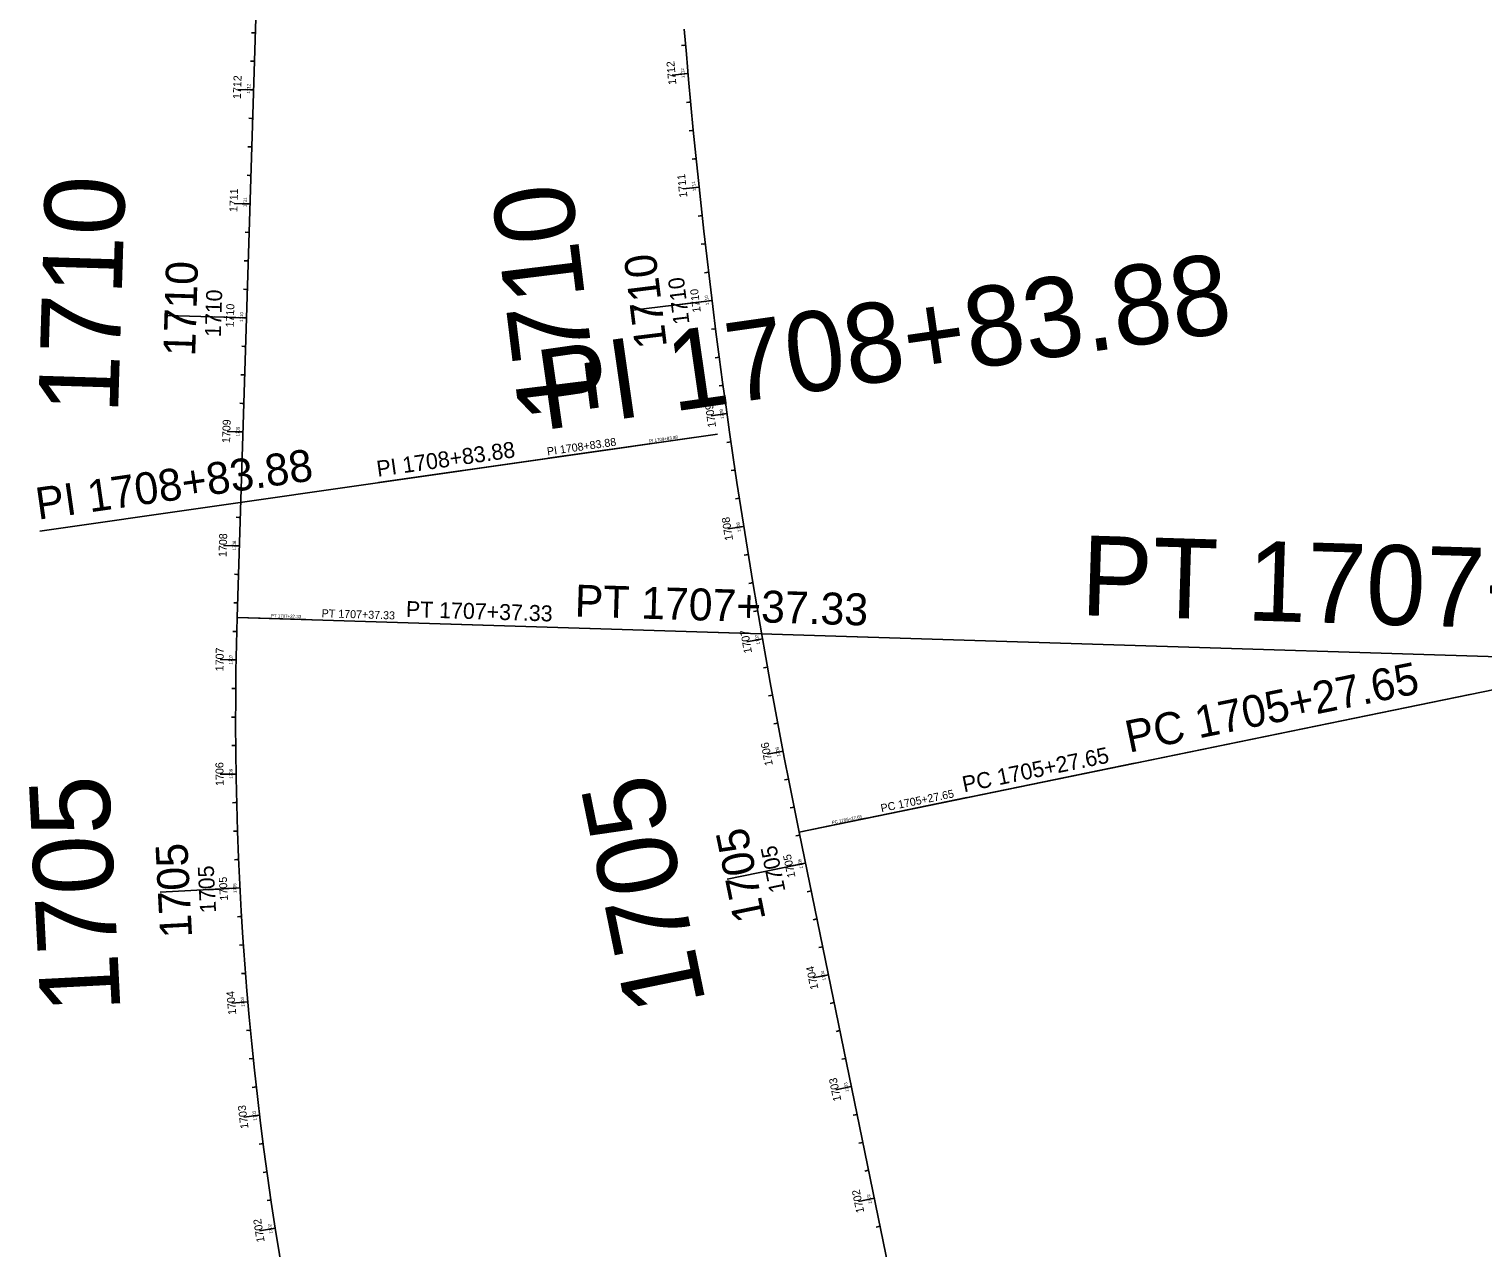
# Model space of a CAD drawing. Extents: x 353835 to 363333, y 126218 to 205387.
# Drawn here: x 361189 to 362463, y 129386 to 130454 of the extents above; entities that cross this region are included whole.
import ezdxf

# ---------------------------------------------------------------- set-up
doc = ezdxf.new("R2010")
doc.units = 0
for name, color, linetype in [('P_ALI_100_PIData', 7, 'Continuous'), ('P_ALI_100_Sta', 7, 'Continuous'), ('P_ALI_100_Tic', 7, 'Continuous'), ('P_ALI_20', 7, 'Continuous'), ('P_ALI_200_PIData', 7, 'Continuous'), ('P_ALI_200_Sta', 7, 'Continuous'), ('P_ALI_200_Tic', 7, 'Continuous'), ('P_ALI_20_PIData', 7, 'Continuous'), ('P_ALI_20_Sta', 7, 'Continuous'), ('P_ALI_20_Tic', 7, 'Continuous'), ('P_ALI_500_PIData', 7, 'Continuous'), ('P_ALI_500_Sta', 7, 'Continuous'), ('P_ALI_50_PIData', 7, 'Continuous'), ('P_ALI_50_Sta', 7, 'Continuous'), ('P_ALI_50_Tic', 7, 'Continuous')]:
    doc.layers.add(name, color=color, linetype=linetype)

msp = doc.modelspace()

# ---------------------------------------------------------------- linework, layer by layer
for points in [[(361766.2, 130415), (361766.3, 130415)], [(361775.9, 130315.4), (361775.9, 130315.5)], [(361800.3, 130117), (361800.4, 130117)], [(361815.1, 130018), (361815.1, 130018)], [(361831.5, 129919.4), (361831.5, 129919.4)], [(361849.5, 129821), (361849.6, 129821.1)], [(361889.3, 129625), (361889.3, 129625.1)], [(361909.4, 129527.1), (361909.5, 129527.1)], [(361929.5, 129429.1), (361929.6, 129429.1)]]:
    msp.add_lwpolyline(points)
at = {"layer": 'P_ALI_100_PIData'}
for points in [[(361792, 130099), (361495.1, 130056.5)], [(361792, 130099), (361732.6, 130090.5)], [(361371.2, 129938.3), (361671, 129929)], [(361371.2, 129938.3), (361431.2, 129936.4)], [(361863.7, 129750.1), (362157.5, 129810.4)], [(361863.7, 129750.1), (361922.4, 129762.2)]]:
    msp.add_lwpolyline(points, dxfattribs=at)
at = {"layer": 'P_ALI_100_Tic'}
for points in [[(361759.3, 130414.4), (361766.3, 130415)], [(361378.6, 130401), (361385.6, 130400.8)], [(361769, 130314.7), (361775.9, 130315.4)], [(361375.5, 130301), (361382.5, 130300.8)], [(361717.8, 130207.6), (361787.3, 130216.1)], [(361773.4, 130214.4), (361787.3, 130216.1)], [(361309.4, 130203.1), (361379.4, 130200.9)], [(361365.4, 130201.3), (361379.4, 130200.9)], [(361793.4, 130116), (361800.4, 130117)], [(361369.3, 130101.1), (361376.3, 130100.9)], [(361808.2, 130017), (361815.1, 130018)], [(361366.1, 130001.2), (361373.1, 130001)], [(361824.6, 129918.2), (361831.5, 129919.4)], [(361363.3, 129901.1), (361370.3, 129901)], [(361842.7, 129819.7), (361849.6, 129821.1)], [(361363.2, 129800.9), (361370.2, 129801)], [(361800.7, 129708.9), (361869.2, 129723)], [(361855.5, 129720.2), (361869.2, 129723)], [(361303.7, 129697.5), (361373.6, 129701.1)], [(361359.6, 129700.4), (361373.6, 129701.1)], [(361882.5, 129623.6), (361889.3, 129625)], [(361373.5, 129600.7), (361380.4, 129601.3)], [(361902.6, 129525.7), (361909.4, 129527.1)], [(361383.8, 129501), (361390.8, 129501.9)], [(361922.7, 129427.7), (361929.6, 129429.1)], [(361397.6, 129401.7), (361404.6, 129402.8)]]:
    msp.add_lwpolyline(points, dxfattribs=at)
at = {"layer": 'P_ALI_20'}
for p, q in [((361371.2, 129938.3), (361462, 132847.8)), ((362324.5, 127505.2), (361863.7, 129750.1))]:
    msp.add_line(p, q, dxfattribs=at)
for centre, radius, start, end in [((367643.2, 130936.5), 5900, 184.68978, 191.60009), ((364244.8, 129848.6), 2875, 178.2122, 207.9813)]:
    msp.add_arc(centre, radius, start, end, dxfattribs=at)
at = {"layer": 'P_ALI_200_PIData'}
for points in [[(361792, 130099), (361198.1, 130014)], [(361371.2, 129938.3), (361970.9, 129919.6)], [(361863.7, 129750.1), (362451.4, 129870.7)]]:
    msp.add_lwpolyline(points, dxfattribs=at)
at = {"layer": 'P_ALI_200_Tic'}
for points in [[(361752.3, 130413.7), (361766.3, 130415)], [(361371.6, 130401.2), (361385.6, 130400.8)], [(361762, 130314), (361775.9, 130315.4)], [(361368.5, 130301.3), (361382.5, 130300.8)], [(361759.5, 130212.7), (361787.3, 130216.1)], [(361351.4, 130201.7), (361379.4, 130200.9)], [(361786.5, 130115), (361800.4, 130117)], [(361362.3, 130101.4), (361376.3, 130100.9)], [(361801.3, 130015.9), (361815.1, 130018)], [(361359.1, 130001.4), (361373.1, 130001)], [(361817.7, 129917), (361831.5, 129919.4)], [(361356.3, 129901.3), (361370.3, 129901)], [(361835.8, 129818.4), (361849.6, 129821.1)], [(361356.2, 129800.8), (361370.2, 129801)], [(361841.8, 129717.4), (361869.2, 129723)], [(361345.6, 129699.6), (361373.6, 129701.1)], [(361875.6, 129622.2), (361889.3, 129625)], [(361366.5, 129600.1), (361380.4, 129601.3)], [(361895.7, 129524.3), (361909.4, 129527.1)], [(361376.9, 129500.2), (361390.8, 129501.9)], [(361915.8, 129426.3), (361929.6, 129429.1)], [(361390.7, 129400.6), (361404.6, 129402.8)]]:
    msp.add_lwpolyline(points, dxfattribs=at)
at = {"layer": 'P_ALI_20_Tic'}
for points in [[(361385.8, 130450.8), (361387.2, 130450.7)], [(361762.7, 130439.8), (361764.1, 130439.9)], [(361385, 130425.8), (361386.4, 130425.8)], [(361763.5, 130414.7), (361766.3, 130415)], [(361382.8, 130400.9), (361385.6, 130400.8)], [(361767.1, 130390), (361768.5, 130390.1)], [(361383.4, 130375.8), (361384.8, 130375.8)], [(361769.5, 130365.1), (361770.9, 130365.2)], [(361382.7, 130350.8), (361384.1, 130350.8)], [(361772, 130340.2), (361773.4, 130340.3)], [(361381.9, 130325.8), (361383.3, 130325.8)], [(361773.2, 130315.2), (361775.9, 130315.4)], [(361379.7, 130300.9), (361382.5, 130300.8)], [(361777.2, 130290.4), (361778.6, 130290.6)], [(361380.3, 130275.9), (361381.7, 130275.8)], [(361780, 130265.6), (361781.4, 130265.8)], [(361379.5, 130250.9), (361380.9, 130250.8)], [(361782.9, 130240.8), (361784.3, 130240.9)], [(361378.8, 130225.9), (361380.2, 130225.9)], [(361784.5, 130215.8), (361787.3, 130216.1)], [(361376.6, 130201), (361379.4, 130200.9)], [(361789, 130191.1), (361790.4, 130191.3)], [(361377.2, 130175.9), (361378.6, 130175.9)], [(361792.2, 130166.3), (361793.6, 130166.5)], [(361376.4, 130150.9), (361377.8, 130150.9)], [(361795.5, 130141.5), (361796.9, 130141.7)], [(361375.6, 130125.9), (361377, 130125.9)], [(361797.6, 130116.6), (361800.4, 130117)], [(361373.5, 130101), (361376.3, 130100.9)], [(361802.5, 130092), (361803.9, 130092.2)], [(361374.1, 130076), (361375.5, 130075.9)], [(361806.1, 130067.3), (361807.5, 130067.5)], [(361373.3, 130051), (361374.7, 130050.9)], [(361809.9, 130042.5), (361811.2, 130042.8)], [(361372.5, 130026), (361373.9, 130026)], [(361812.3, 130017.6), (361815.1, 130018)], [(361370.3, 130001.1), (361373.1, 130001)], [(361817.6, 129993.1), (361819, 129993.4)], [(361371, 129976), (361372.4, 129976)], [(361821.7, 129968.5), (361823.1, 129968.7)], [(361370.2, 129951), (361371.6, 129951)], [(361825.8, 129943.8), (361827.2, 129944)], [(361369.4, 129926), (361370.8, 129926)], [(361828.7, 129918.9), (361831.5, 129919.4)], [(361367.5, 129901.1), (361370.3, 129901)], [(361834.5, 129894.5), (361835.8, 129894.8)], [(361368.5, 129876), (361369.9, 129876)], [(361838.9, 129869.9), (361840.3, 129870.2)], [(361368.4, 129851), (361369.8, 129851)], [(361843.5, 129845.4), (361844.9, 129845.6)], [(361368.5, 129826), (361369.9, 129826)], [(361846.8, 129820.5), (361849.6, 129821.1)], [(361367.4, 129801), (361370.2, 129801)], [(361853, 129796.2), (361854.3, 129796.5)], [(361369.3, 129776), (361370.7, 129776)], [(361857.8, 129771.7), (361859.2, 129772)], [(361370, 129751), (361371.4, 129751)], [(361862.8, 129747.2), (361864.2, 129747.5)], [(361371, 129726), (361372.4, 129726)], [(361866.5, 129722.4), (361869.2, 129723)], [(361370.8, 129700.9), (361373.6, 129701.1)], [(361872.9, 129698.2), (361874.3, 129698.5)], [(361373.6, 129676), (361375, 129676.1)], [(361877.9, 129673.7), (361879.3, 129674)], [(361375.2, 129651.1), (361376.6, 129651.2)], [(361882.9, 129649.3), (361884.3, 129649.5)], [(361377, 129626.1), (361378.4, 129626.2)], [(361886.6, 129624.5), (361889.3, 129625)], [(361377.7, 129601.1), (361380.4, 129601.3)], [(361893, 129600.3), (361894.4, 129600.6)], [(361381.3, 129576.3), (361382.7, 129576.4)], [(361898, 129575.8), (361899.4, 129576.1)], [(361383.8, 129551.4), (361385.2, 129551.5)], [(361903, 129551.3), (361904.4, 129551.6)], [(361386.5, 129526.5), (361387.9, 129526.7)], [(361906.7, 129526.5), (361909.4, 129527.1)], [(361388, 129501.5), (361390.8, 129501.9)], [(361913.1, 129502.3), (361914.5, 129502.6)], [(361392.5, 129476.9), (361393.9, 129477.1)], [(361918.1, 129477.8), (361919.5, 129478.1)], [(361395.9, 129452.1), (361397.2, 129452.3)], [(361923.2, 129453.3), (361924.5, 129453.6)], [(361926.8, 129428.6), (361929.6, 129429.1)], [(361399.4, 129427.3), (361400.8, 129427.5)], [(361933.2, 129404.4), (361934.6, 129404.6)], [(361401.8, 129402.4), (361404.6, 129402.8)]]:
    msp.add_lwpolyline(points, dxfattribs=at)
at = {"layer": 'P_ALI_500_PIData'}
for points in [[(361792, 130099), (361643.6, 130077.8)], [(361863.7, 129750.1), (363333, 130051.7)], [(361371.2, 129938.3), (362870.5, 129891.5)]]:
    msp.add_lwpolyline(points, dxfattribs=at)
at = {"layer": 'P_ALI_50_PIData'}
for points in [[(361792, 130099), (361643.6, 130077.8)], [(361371.2, 129938.3), (361521.1, 129933.6)], [(361371.2, 129938.3), (361521.1, 129933.6)], [(361863.7, 129750.1), (362010.6, 129780.3)]]:
    msp.add_lwpolyline(points, dxfattribs=at)
at = {"layer": 'P_ALI_50_Tic'}
for points in [[(361383.7, 130450.9), (361387.2, 130450.7)], [(361383.7, 130450.9), (361387.2, 130450.7)], [(361760.6, 130439.6), (361764.1, 130439.9)], [(361382.9, 130425.9), (361386.4, 130425.8)], [(361382.9, 130425.9), (361386.4, 130425.8)], [(361759.3, 130414.4), (361766.3, 130415)], [(361378.6, 130401), (361385.6, 130400.8)], [(361378.6, 130401), (361385.6, 130400.8)], [(361765, 130389.8), (361768.5, 130390.1)], [(361381.3, 130375.9), (361384.8, 130375.8)], [(361381.3, 130375.9), (361384.8, 130375.8)], [(361767.4, 130364.9), (361770.9, 130365.2)], [(361380.6, 130350.9), (361384.1, 130350.8)], [(361380.6, 130350.9), (361384.1, 130350.8)], [(361769.9, 130340), (361773.4, 130340.3)], [(361379.8, 130325.9), (361383.3, 130325.8)], [(361379.8, 130325.9), (361383.3, 130325.8)], [(361769, 130314.7), (361775.9, 130315.4)], [(361375.5, 130301), (361382.5, 130300.8)], [(361375.5, 130301), (361382.5, 130300.8)], [(361775.1, 130290.2), (361778.6, 130290.6)], [(361378.2, 130275.9), (361381.7, 130275.8)], [(361378.2, 130275.9), (361381.7, 130275.8)], [(361777.9, 130265.4), (361781.4, 130265.8)], [(361377.4, 130251), (361380.9, 130250.8)], [(361377.4, 130251), (361380.9, 130250.8)], [(361780.8, 130240.5), (361784.3, 130240.9)], [(361376.7, 130226), (361380.2, 130225.9)], [(361376.7, 130226), (361380.2, 130225.9)], [(361780.4, 130215.2), (361787.3, 130216.1)], [(361372.4, 130201.1), (361379.4, 130200.9)], [(361372.4, 130201.1), (361379.4, 130200.9)], [(361786.9, 130190.9), (361790.4, 130191.3)], [(361375.1, 130176), (361378.6, 130175.9)], [(361375.1, 130176), (361378.6, 130175.9)], [(361790.1, 130166), (361793.6, 130166.5)], [(361374.3, 130151), (361377.8, 130150.9)], [(361374.3, 130151), (361377.8, 130150.9)], [(361793.5, 130141.2), (361796.9, 130141.7)], [(361373.5, 130126), (361377, 130125.9)], [(361373.5, 130126), (361377, 130125.9)], [(361793.4, 130116), (361800.4, 130117)], [(361369.3, 130101.1), (361376.3, 130100.9)], [(361369.3, 130101.1), (361376.3, 130100.9)], [(361800.4, 130091.7), (361803.9, 130092.2)], [(361372, 130076), (361375.5, 130075.9)], [(361372, 130076), (361375.5, 130075.9)], [(361804, 130067), (361807.5, 130067.5)], [(361371.2, 130051), (361374.7, 130050.9)], [(361371.2, 130051), (361374.7, 130050.9)], [(361807.8, 130042.2), (361811.2, 130042.8)], [(361370.4, 130026.1), (361373.9, 130026)], [(361370.4, 130026.1), (361373.9, 130026)], [(361808.2, 130017), (361815.1, 130018)], [(361366.1, 130001.2), (361373.1, 130001)], [(361366.1, 130001.2), (361373.1, 130001)], [(361815.6, 129992.8), (361819, 129993.4)], [(361368.9, 129976.1), (361372.4, 129976)], [(361368.9, 129976.1), (361372.4, 129976)], [(361819.6, 129968.1), (361823.1, 129968.7)], [(361368.1, 129951.1), (361371.6, 129951)], [(361368.1, 129951.1), (361371.6, 129951)], [(361823.8, 129943.4), (361827.2, 129944)], [(361367.3, 129926.1), (361370.8, 129926)], [(361367.3, 129926.1), (361370.8, 129926)], [(361824.6, 129918.2), (361831.5, 129919.4)], [(361363.3, 129901.1), (361370.3, 129901)], [(361363.3, 129901.1), (361370.3, 129901)], [(361832.4, 129894.2), (361835.8, 129894.8)], [(361366.4, 129876), (361369.9, 129876)], [(361366.4, 129876), (361369.9, 129876)], [(361836.9, 129869.6), (361840.3, 129870.2)], [(361366.3, 129851), (361369.8, 129851)], [(361366.3, 129851), (361369.8, 129851)], [(361841.4, 129845), (361844.9, 129845.6)], [(361366.4, 129826), (361369.9, 129826)], [(361366.4, 129826), (361369.9, 129826)], [(361842.7, 129819.7), (361849.6, 129821.1)], [(361363.2, 129800.9), (361370.2, 129801)], [(361363.2, 129800.9), (361370.2, 129801)], [(361850.9, 129795.8), (361854.3, 129796.5)], [(361367.2, 129775.9), (361370.7, 129776)], [(361367.2, 129775.9), (361370.7, 129776)], [(361855.8, 129771.3), (361859.2, 129772)], [(361367.9, 129750.9), (361371.4, 129751)], [(361367.9, 129750.9), (361371.4, 129751)], [(361860.8, 129746.8), (361864.2, 129747.5)], [(361368.9, 129725.9), (361372.4, 129726)], [(361368.9, 129725.9), (361372.4, 129726)], [(361862.4, 129721.6), (361869.2, 129723)], [(361366.6, 129700.7), (361373.6, 129701.1)], [(361366.6, 129700.7), (361373.6, 129701.1)], [(361870.8, 129697.8), (361874.3, 129698.5)], [(361371.5, 129675.9), (361375, 129676.1)], [(361371.5, 129675.9), (361375, 129676.1)], [(361875.9, 129673.3), (361879.3, 129674)], [(361373.1, 129650.9), (361376.6, 129651.2)], [(361373.1, 129650.9), (361376.6, 129651.2)], [(361880.9, 129648.8), (361884.3, 129649.5)], [(361374.9, 129626), (361378.4, 129626.2)], [(361374.9, 129626), (361378.4, 129626.2)], [(361882.5, 129623.6), (361889.3, 129625)], [(361373.5, 129600.7), (361380.4, 129601.3)], [(361373.5, 129600.7), (361380.4, 129601.3)], [(361890.9, 129599.9), (361894.4, 129600.6)], [(361379.2, 129576.1), (361382.7, 129576.4)], [(361379.2, 129576.1), (361382.7, 129576.4)], [(361896, 129575.4), (361899.4, 129576.1)], [(361381.7, 129551.2), (361385.2, 129551.5)], [(361381.7, 129551.2), (361385.2, 129551.5)], [(361901, 129550.9), (361904.4, 129551.6)], [(361384.4, 129526.3), (361387.9, 129526.7)], [(361384.4, 129526.3), (361387.9, 129526.7)], [(361902.6, 129525.7), (361909.4, 129527.1)], [(361383.8, 129501), (361390.8, 129501.9)], [(361383.8, 129501), (361390.8, 129501.9)], [(361911, 129501.9), (361914.5, 129502.6)], [(361390.4, 129476.6), (361393.9, 129477.1)], [(361390.4, 129476.6), (361393.9, 129477.1)], [(361916.1, 129477.4), (361919.5, 129478.1)], [(361393.8, 129451.8), (361397.2, 129452.3)], [(361393.8, 129451.8), (361397.2, 129452.3)], [(361921.1, 129452.9), (361924.5, 129453.6)], [(361922.7, 129427.7), (361929.6, 129429.1)], [(361397.3, 129427), (361400.8, 129427.5)], [(361397.3, 129427), (361400.8, 129427.5)], [(361931.2, 129403.9), (361934.6, 129404.6)], [(361397.6, 129401.7), (361404.6, 129402.8)], [(361397.6, 129401.7), (361404.6, 129402.8)]]:
    msp.add_lwpolyline(points, dxfattribs=at)

# ---------------------------------------------------------------- texts
at = {"layer": 'P_ALI_100_PIData'}
for s, rotation, p in [('PI 1708+83.88', 8.1449, (361494.4, 130061.5)), ('PT 1707+37.33', 358.2122, (361518.9, 129938.7)), ('PC 1705+27.65', 11.6001, (362008.2, 129784.9))]:
    msp.add_text(s, height=14, rotation=rotation, dxfattribs=at).set_placement(p)
at = {"layer": 'P_ALI_100_Sta'}
for s, rotation, p in [('1710', 97.0131, (361767.6, 130195.9)), ('1710', 88.2122, (361356.8, 130183.9)), ('1705', 101.6001, (361851.8, 129698.5)), ('1705', 92.9418, (361352.7, 129679.5))]:
    msp.add_text(s, height=14, rotation=rotation, dxfattribs=at).set_placement(p)
at = {"layer": 'P_ALI_200_PIData'}
for s, rotation, p in [('PI 1708+83.88', 8.1449, (361196.7, 130023.9)), ('PT 1707+37.33', 358.2122, (361666.7, 129939.1)), ('PC 1705+27.65', 11.6001, (362152.7, 129819.6))]:
    msp.add_text(s, height=28, rotation=rotation, dxfattribs=at).set_placement(p)
at = {"layer": 'P_ALI_200_Sta'}
for s, rotation, p in [('1710', 88.2122, (361334.3, 130167)), ('1710', 97.0131, (361747.9, 130175.7)), ('1705', 101.6001, (361834.4, 129674)), ('1705', 92.9418, (361331.7, 129657.9))]:
    msp.add_text(s, height=28, rotation=rotation, dxfattribs=at).set_placement(p)
at = {"layer": 'P_ALI_20_PIData'}
for s, rotation, p in [('PI 1708+83.88', 8.1449, (361732.5, 130091.5)), ('PT 1707+37.33', 358.2122, (361400.7, 129938.4)), ('PC 1705+27.65', 11.6001, (361892.6, 129757))]:
    msp.add_text(s, height=2.8, rotation=rotation, dxfattribs=at).set_placement(p)
at = {"layer": 'P_ALI_20_Sta'}
for s, rotation, p in [('1712', 95.0708, (361763.5, 130411.3)), ('1712', 88.2122, (361382.4, 130397.5)), ('1711', 96.042, (361773.2, 130312.1)), ('1711', 88.2122, (361379.3, 130297.9)), ('1710', 97.0131, (361784.7, 130212.2)), ('1710', 88.2122, (361376.2, 130197.4)), ('1709', 97.9842, (361797.9, 130112.5)), ('1709', 88.2122, (361373.1, 130096.9)), ('1708', 98.9553, (361812.7, 130013.5)), ('1708', 88.2122, (361369.9, 129997)), ('1707', 99.9264, (361829.2, 129914.8)), ('1707', 88.956, (361367.1, 129897)), ('1706', 100.8975, (361847.3, 129816.5)), ('1706', 90.9489, (361367.2, 129796.9)), ('1705', 101.6001, (361867, 129718.4)), ('1705', 92.9418, (361370.7, 129696.8)), ('1704', 101.6001, (361887.1, 129620.4)), ('1704', 94.9347, (361377.7, 129597)), ('1703', 101.6001, (361907.3, 129522.5)), ('1703', 96.9276, (361388.2, 129497.4)), ('1702', 101.6001, (361927.4, 129424.5)), ('1702', 98.9205, (361402.2, 129398.3))]:
    msp.add_text(s, height=2.8, rotation=rotation, dxfattribs=at).set_placement(p)
at = {"layer": 'P_ALI_500_PIData'}
for s, rotation, p in [('PI 1708+83.88', 8.1449, (361640, 130102.5)), ('PT 1707+37.33', 358.2122, (362109.9, 129940.3))]:
    msp.add_text(s, height=70, rotation=rotation, dxfattribs=at).set_placement(p)
at = {"layer": 'P_ALI_500_Sta'}
for s, rotation, p in [('1710', 88.2122, (361266.7, 130116.2)), ('1710', 97.0131, (361688.9, 130115.1)), ('1705', 92.9418, (361269, 129593)), ('1705', 101.6001, (361782.1, 129600.5))]:
    msp.add_text(s, height=70, rotation=rotation, dxfattribs=at).set_placement(p)
at = {"layer": 'P_ALI_50_PIData'}
for s, rotation, p in [('PI 1708+83.88', 8.1449, (361643.2, 130080.3)), ('PT 1707+37.33', 358.2122, (361445.1, 129938.5)), ('PT 1707+37.33', 358.2122, (361445.1, 129938.5)), ('PC 1705+27.65', 11.6001, (361935.9, 129767.5))]:
    msp.add_text(s, height=7, rotation=rotation, dxfattribs=at).set_placement(p)
at = {"layer": 'P_ALI_50_Sta'}
for s, rotation, p in [('1712', 95.0708, (361756.1, 130405.5)), ('1712', 88.2122, (361374.4, 130392.6)), ('1712', 88.2122, (361374.4, 130392.6)), ('1711', 96.042, (361765.8, 130306.7)), ('1711', 88.2122, (361371.3, 130293.5)), ('1711', 88.2122, (361371.3, 130293.5)), ('1710', 97.0131, (361777.5, 130206)), ('1710', 88.2122, (361368.1, 130192.4)), ('1710', 88.2122, (361368.1, 130192.4)), ('1709', 97.9842, (361790.9, 130105.3)), ('1709', 88.2122, (361364.9, 130091)), ('1709', 88.2122, (361364.9, 130091)), ('1708', 98.9553, (361805.8, 130006.2)), ('1708', 88.2122, (361361.8, 129991.1)), ('1708', 88.2122, (361361.8, 129991.1)), ('1707', 99.9264, (361822.4, 129907.4)), ('1707', 88.956, (361359.1, 129891)), ('1707', 88.956, (361359.1, 129891)), ('1706', 100.8975, (361840.7, 129808.9)), ('1706', 90.9489, (361359.4, 129790.6)), ('1706', 90.9489, (361359.4, 129790.6)), ('1705', 101.6001, (361860.5, 129710.8)), ('1705', 92.9418, (361363.1, 129690.3)), ('1705', 92.9418, (361363.1, 129690.3)), ('1704', 101.6001, (361880.6, 129612.8)), ('1704', 94.9347, (361370.4, 129590.2)), ('1704', 94.9347, (361370.4, 129590.2)), ('1703', 101.6001, (361900.7, 129514.8)), ('1703', 96.9276, (361381.1, 129490.4)), ('1703', 96.9276, (361381.1, 129490.4)), ('1702', 101.6001, (361920.8, 129416.9)), ('1702', 98.9205, (361395.3, 129391)), ('1702', 98.9205, (361395.3, 129391))]:
    msp.add_text(s, height=7, rotation=rotation, dxfattribs=at).set_placement(p)

doc.saveas('drawing.dxf')
